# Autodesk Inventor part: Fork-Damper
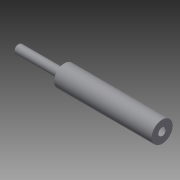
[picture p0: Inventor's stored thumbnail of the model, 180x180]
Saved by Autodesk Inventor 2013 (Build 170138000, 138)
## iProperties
Shininess: 64.0
Length Units: 11272
Angle Units: 11279
Time Units: 11290
Mass Units: 11286
Length Display Precision: 3
Angle Display Precision: 2
Compacted: True
Created: 2001-11
Part Number: Fork-Damper
Document SubType Name: Modeling
Designer: Autodesk, Inc.
Mass: 13.3721 g
Surface Area: 211.026 cm^2
Volume: 13.3721 cm^3
Density: 1 g/cm^3
Material: Generic
Density: 0.0
Volumn: 0.0
Area: 0.0
PropertySet Name: Model Information
Control State: 0
Master: False
Checked Out: False
Author: Autodesk, Inc.
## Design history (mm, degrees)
sketch "Sketch1"
  geometry: L1 (32.17, 83.081)-(30.9, 81.811); L2 (85.51, 83.081)-(32.17, 83.081); L3 (85.51, 90.32)-(85.51, 83.081); L4 (199.81, 90.32)-(85.51, 90.32); L5 (199.81, 78.064)-(199.81, 90.32); L6 (30.9, 78.064)-(199.81, 78.064); L7 (30.9, 81.811)-(30.9, 78.064); L8 (30.9, 78.064)-(198.54, 78.064)
  constraints: 16 end point, 3 horizontal, 3 vertical, 1 point on line, 1 other
  dimensions: "d3" = 53.34 distance of L2.start L1.start; "d7" = 114.3 distance of L4.start L3.start
revolve "RevolutionFull1" sketch "Sketch1" stored, may be unused: angle "d8" = 360 deg
shell "Shell1" dims "d9" = 1.27
sketch "Sketch2"
  geometry: C1 r 12.256 at (0, 0) reference
hole "Hole1" sketch "Sketch2" at (0, 0) diameter "d10" = 8.89; stored, may be unused: countersink angle "d14" = 82 deg, drill point angle "d16" = 118 deg; dims "d11" = 12.7, "d12" = 9.525, "d13" = 6.35, "d15" = 19.05
body "Solid1"
other parameters: "d0" = 205.74 (derived), "d2" = 53.34 (derived), "d4" = 38.1 (derived), "d6" = 114.3 (derived)
